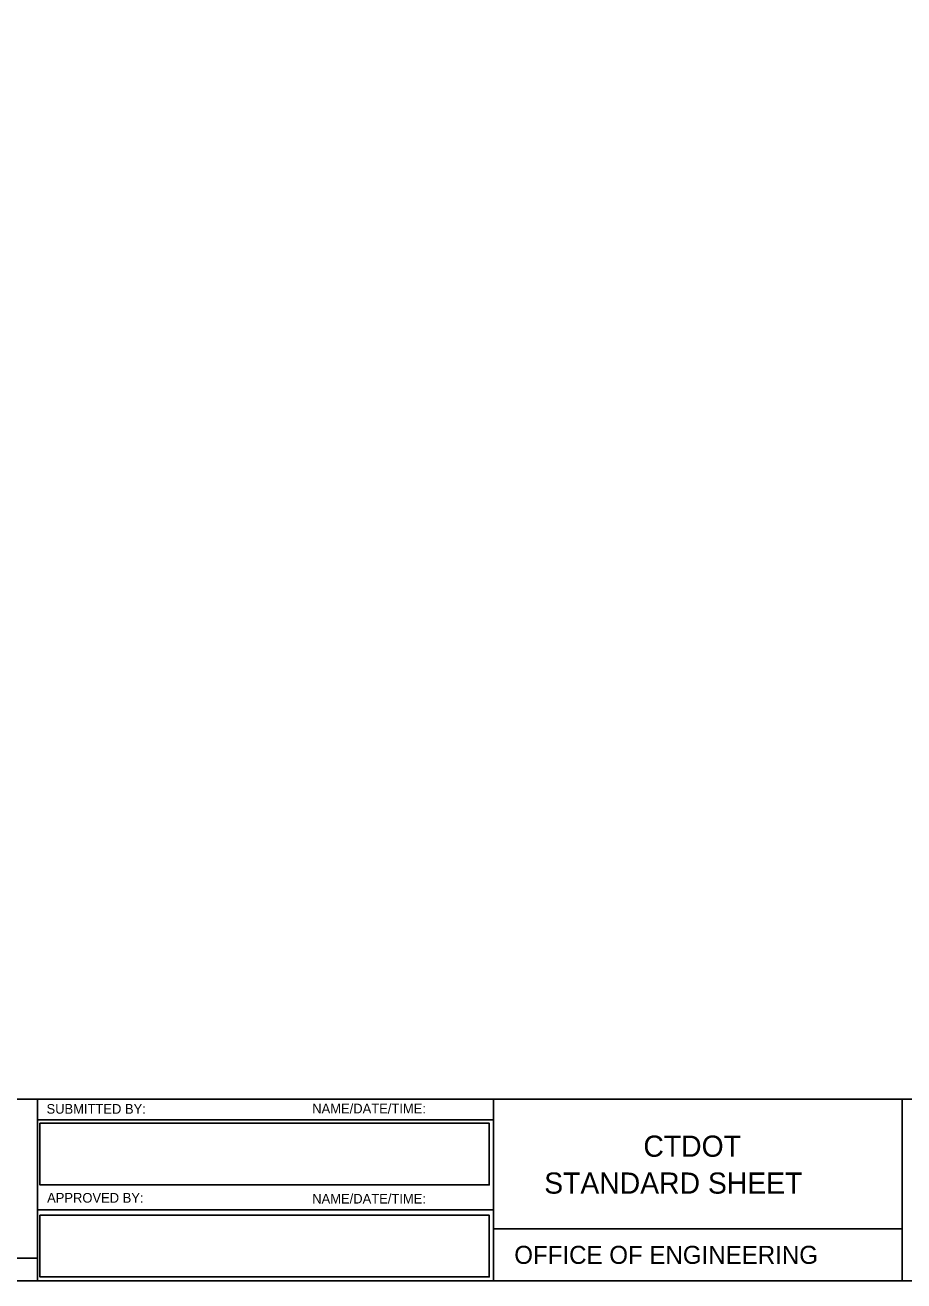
# Model space of a CAD drawing. Extents: x 0 to 1270, y 0 to 830.
# Drawn here: x 647.8 to 938.1, y 0 to 415 of the extents above; entities that cross this region are included whole.
import ezdxf

# ---------------------------------------------------------------- set-up
doc = ezdxf.new("R2010")
doc.units = 0
for name, color, linetype in [('CT_Border_Perimeter_Shape', 7, 'Continuous'), ('CT_DigSig_Field1', 7, 'Continuous'), ('CT_DigSig_Field2', 7, 'Continuous'), ('CT_Signature_Field_CTDOT', 7, 'Continuous'), ('CT_Title_Block_Linework', 7, 'Continuous'), ('CT_Title_Block_Text', 7, 'Continuous')]:
    doc.layers.add(name, color=color, linetype=linetype)

msp = doc.modelspace()

# ---------------------------------------------------------------- linework, layer by layer
at = {"layer": 'CT_Border_Perimeter_Shape'}
msp.add_lwpolyline([(0, 0), (1270, 0), (1270, 830), (0, 830)], close=True, dxfattribs=at)
at = {"layer": 'CT_DigSig_Field1'}
msp.add_lwpolyline([(652.67, 52.09), (801.15, 52.09), (801.15, 31.73), (652.67, 31.73)], close=True, dxfattribs=at)
at = {"layer": 'CT_DigSig_Field2'}
msp.add_lwpolyline([(652.67, 21.67), (801.15, 21.67), (801.15, 1.32), (652.67, 1.32)], close=True, dxfattribs=at)
at = {"layer": 'CT_Signature_Field_CTDOT'}
for p, q in [((651.86, 53.22), (802.52, 53.22)), ((651.86, 23.43), (802.52, 23.43))]:
    msp.add_line(p, q, dxfattribs=at)
at = {"layer": 'CT_Title_Block_Linework'}
for p, q in [((1270, 60), (0, 60)), ((651.86, 60), (651.86, 0)), ((802.52, 60), (802.52, 0)), ((937.58, 0), (937.58, 60)), ((937.58, 17.22), (802.52, 17.22)), ((651.86, 7.5), (435.95, 7.5))]:
    msp.add_line(p, q, dxfattribs=at)

# ---------------------------------------------------------------- texts
at = {"layer": 'CT_Signature_Field_CTDOT'}
for s, height, p in [('NAME/DATE/TIME:', 3.2, (742.67, 55.36)), ('CTDOT', 7, (852.08, 41.02)), ('STANDARD SHEET', 7, (819.31, 28.82)), ('APPROVED BY:  ', 3.2, (655.07, 25.85)), ('NAME/DATE/TIME:', 3.2, (742.67, 25.56)), ('OFFICE OF ENGINEERING', 5.95, (809.42, 5.63))]:
    msp.add_text(s, height=height, dxfattribs=at).set_placement(p)
at = {"layer": 'CT_Title_Block_Text'}
msp.add_text('SUBMITTED BY:', height=3.2, dxfattribs=at).set_placement((654.88, 55.25))

doc.saveas('drawing.dxf')
